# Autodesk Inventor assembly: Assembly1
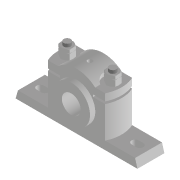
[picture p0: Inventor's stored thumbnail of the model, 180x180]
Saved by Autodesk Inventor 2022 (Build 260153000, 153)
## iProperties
Created: 2021-03
Part Number: Assembly1
Document SubType Name: Assembly
Designer: ASUS Laptop
Author: ASUS Laptop
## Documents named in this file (7)
- D:\PROJECTS_2021\Resources\Tutorial Files\c09_Inv_2022_tut\c09_Inv_2021_tut\c09_Inv_tut_2021\c09_tut02_inv\Plummer Block\Plummer Block.iam
- D:\PROJECTS_2021\Resources\Tutorial Files\c09_Inv_2022_tut\c09_Inv_2021_tut\c09_Inv_tut_2021\c09_tut02_inv\Plummer Block\Casting.ipt
- D:\PROJECTS_2021\Resources\Tutorial Files\c09_Inv_2022_tut\c09_Inv_2021_tut\c09_Inv_tut_2021\c09_tut02_inv\Plummer Block\Brasses.ipt
- D:\PROJECTS_2021\Resources\Tutorial Files\c09_Inv_2022_tut\c09_Inv_2021_tut\c09_Inv_tut_2021\c09_tut02_inv\Plummer Block\Cap.ipt
- D:\PROJECTS_2021\Resources\Tutorial Files\c09_Inv_2022_tut\c09_Inv_2021_tut\c09_Inv_tut_2021\c09_tut02_inv\Plummer Block\Bolt.ipt
- D:\PROJECTS_2021\Resources\Tutorial Files\c09_Inv_2022_tut\c09_Inv_2021_tut\c09_Inv_tut_2021\c09_tut02_inv\Plummer Block\Nut.ipt
- D:\PROJECTS_2021\Resources\Tutorial Files\c09_Inv_2022_tut\c09_Inv_2021_tut\c09_Inv_tut_2021\c09_tut02_inv\Plummer Block\locknut.ipt
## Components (9 placed, 6 different names)
1. Casting:1 — Mate:1, Mate:2, Insert:1, Insert:2, Angle:1, Angle:2
2. Brasses:1 — Mate:1, Mate:2, Mate:3, Mate:4
3. Cap:1 — Mate:3, Mate:4, Insert:3, Insert:5
4. Bolt:1 — Insert:2, Angle:1
5. Bolt:2 — Insert:1, Angle:2
6. Nut:1 — Insert:5, Insert:6
7. Nut:2 — Insert:3, Insert:4
8. locknut:1 — Insert:4
9. locknut:2 — Insert:6
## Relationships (12: Insert 6, Mate 4, Angle 2)
- Mate:1: Casting:1 ↔ Brasses:1
- Mate:2: Casting:1 ↔ Brasses:1
- Mate:3: Brasses:1 ↔ Cap:1
- Mate:4: Brasses:1 ↔ Cap:1
- Insert:1: Casting:1 ↔ Bolt:2
- Insert:2: Casting:1 ↔ Bolt:1
- Angle:1: Casting:1 ↔ Bolt:1
- Angle:2: Casting:1 ↔ Bolt:2
- Insert:3: Cap:1 ↔ Nut:2
- Insert:4: Nut:2 ↔ locknut:1
- Insert:5: Cap:1 ↔ Nut:1
- Insert:6: Nut:1 ↔ locknut:2
